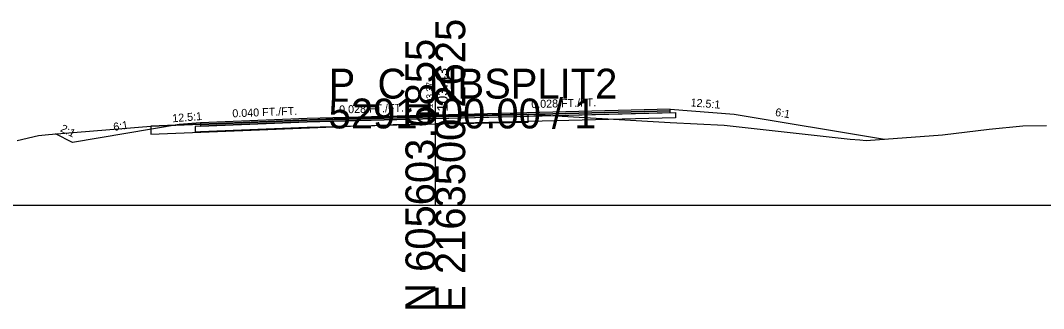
# Model space of a CAD drawing. Extents: x -26 to 1303, y -10 to 12038.
# Drawn here: x 111.1 to 207, y 5990.3 to 6017.3 of the extents above; entities that cross this region are included whole.
import ezdxf

# ---------------------------------------------------------------- set-up
doc = ezdxf.new("R2010")
doc.units = 0
for name, color, linetype in [('RD_GPK_XS_Cell', 7, 'Continuous'), ('RD_XS_Base', 7, 'Continuous'), ('RD_XS_ExGround', 7, 'Continuous'), ('RD_XS_ExPaveRet', 7, 'Continuous'), ('RD_XS_Greenside', 7, 'Continuous'), ('RD_XS_Pave', 7, 'Continuous'), ('RD_XS_PaveOvlay_CP', 7, 'Continuous'), ('RD_XS_TieSlope', 7, 'Continuous'), ('RD_XS_TX_Elev_EX', 7, 'Continuous'), ('RD_XS_TX_Elev_PR', 7, 'Continuous'), ('RD_XS_TX_ShdSlope', 7, 'Continuous'), ('RD_XS_TX_Slope', 7, 'Continuous')]:
    doc.layers.add(name, color=color, linetype=linetype)

msp = doc.modelspace()

# ---------------------------------------------------------------- linework, layer by layer
at = {"layer": 'RD_GPK_XS_Cell'}
for p, q in [((150, 6000), (150, 6010)), ((0, 6000), (150, 6000)), ((150, 6000), (300, 6000))]:
    msp.add_line(p, q, dxfattribs=at)
at = {"layer": 'RD_XS_Base'}
for p, q in [((150, 6008.116), (172.5, 6008.701)), ((150, 6007.616), (150, 6008.275)), ((150, 6008.275), (150, 6008.275)), ((150, 6008.275), (150, 6008.275)), ((150, 6008.275), (150, 6008.116)), ((172.5, 6008.701), (172.5, 6008.201)), ((172.5, 6008.668), (172.5, 6008.668)), ((128, 6007.404), (127.5, 6007.384)), ((127.5, 6007.384), (127.5, 6007.384)), ((127.5, 6007.384), (127.5, 6006.884)), ((138, 6007.804), (128, 6007.404)), ((128, 6007.404), (128, 6007.404)), ((128, 6006.904), (138, 6007.304)), ((150, 6008.116), (138, 6007.804)), ((138, 6007.804), (138, 6007.804)), ((138, 6007.304), (150, 6007.616)), ((138, 6007.304), (138, 6007.304)), ((172.5, 6008.201), (150, 6007.616)), ((150, 6008.116), (150, 6008.116)), ((150, 6007.616), (150, 6008.116)), ((150, 6008.116), (150, 6008.116)), ((150, 6008.116), (150, 6008.116)), ((150, 6007.616), (150, 6007.616)), ((127.5, 6006.884), (128, 6006.904)), ((128, 6006.904), (128, 6006.904))]:
    msp.add_line(p, q, dxfattribs=at)
at = {"layer": 'RD_XS_ExGround'}
msp.add_lwpolyline([(110.806, 6006.081), (112.833, 6006.551), (113.74, 6006.633), (123.35, 6007.417), (139.004, 6008.034), (142.785, 6008.182), (143.202, 6008.196), (144.342, 6008.238), (146.057, 6008.303), (148.56, 6008.342), (158.682, 6008.536), (172.001, 6007.762), (177.051, 6007.512), (188.856, 6006.207), (189.771, 6006.119), (190.368, 6006.053), (197.524, 6006.59), (201.892, 6007.129), (205.042, 6007.446), (207.267, 6007.473)], dxfattribs=at)
at = {"layer": 'RD_XS_ExPaveRet'}
for points in [[(148.56, 6008.342), (146.057, 6008.303), (146.057, 6008.303), (144.342, 6008.238), (144.342, 6008.238), (143.202, 6008.196), (143.202, 6008.196), (142.785, 6008.182), (139.004, 6008.034), (139.004, 6008.034), (123.35, 6007.417), (123.35, 6007.417), (123.35, 6007.417), (123.35, 6006.667), (123.35, 6006.667), (139.004, 6007.284), (139.004, 6007.284), (142.785, 6007.432), (143.202, 6007.446), (143.202, 6007.446), (144.342, 6007.488), (144.342, 6007.488), (146.057, 6007.553), (146.057, 6007.553), (148.56, 6007.592), (148.56, 6007.592), (158.682, 6007.786), (158.682, 6008.536), (158.682, 6008.536), (148.56, 6008.342), (148.56, 6008.342)], [(148.56, 6008.342), (146.057, 6008.303), (144.342, 6008.238), (143.202, 6008.196), (142.785, 6008.182), (139.004, 6008.034), (123.35, 6007.417), (123.35, 6006.667), (139.004, 6007.284), (142.785, 6007.432), (143.202, 6007.446), (144.342, 6007.488), (146.057, 6007.553), (148.56, 6007.592), (158.682, 6007.786), (158.682, 6008.536), (148.56, 6008.342)]]:
    msp.add_lwpolyline(points, dxfattribs=at)
at = {"layer": 'RD_XS_Greenside'}
for p, q in [((178, 6008.526), (192.071, 6006.181)), ((126, 6007.562), (116, 6005.895)), ((116, 6005.895), (114.413, 6006.688))]:
    msp.add_line(p, q, dxfattribs=at)
at = {"layer": 'RD_XS_Pave'}
for p, q in [((150, 6008.434), (138, 6008.122)), ((138, 6007.963), (150, 6008.275)), ((150, 6008.275), (138, 6007.963)), ((172, 6009.006), (150, 6008.434)), ((172, 6008.847), (150, 6008.275)), ((150, 6008.275), (172, 6008.847)), ((150, 6008.116), (172, 6008.688)), ((150, 6008.434), (150, 6008.434)), ((150, 6008.275), (150, 6008.275)), ((150, 6008.275), (150, 6008.275)), ((150, 6008.275), (150, 6008.116)), ((150, 6008.275), (150, 6008.275)), ((150, 6008.116), (150, 6008.275)), ((150, 6008.275), (150, 6008.275)), ((150, 6008.275), (150, 6008.275)), ((172, 6008.847), (172, 6009.006)), ((172, 6009.006), (172, 6009.006)), ((172, 6009.006), (172, 6009.006)), ((172, 6009.006), (172, 6009.006)), ((172, 6008.688), (172, 6008.847)), ((172, 6008.847), (172, 6008.847)), ((172, 6008.847), (172, 6008.847)), ((172, 6008.847), (172, 6008.847)), ((172, 6008.847), (172, 6008.847)), ((172, 6008.847), (172, 6008.847)), ((138, 6008.122), (128, 6007.722)), ((128, 6007.563), (138, 6007.963)), ((138, 6007.963), (128, 6007.563)), ((128, 6007.404), (138, 6007.804)), ((128, 6007.722), (128, 6007.722)), ((128, 6007.722), (128, 6007.563)), ((128, 6007.563), (128, 6007.563)), ((128, 6007.563), (128, 6007.404)), ((138, 6008.122), (138, 6008.122)), ((138, 6007.804), (150, 6008.116)), ((138, 6007.963), (138, 6007.963)), ((138, 6007.963), (138, 6007.963)), ((138, 6007.804), (138, 6007.804)), ((150, 6008.116), (150, 6008.116)), ((150, 6008.116), (150, 6008.116))]:
    msp.add_line(p, q, dxfattribs=at)
at = {"layer": 'RD_XS_PaveOvlay_CP'}
for p, q in [((150, 6008.434), (138, 6008.122)), ((172, 6009.006), (150, 6008.434)), ((150, 6008.434), (150, 6008.434)), ((172, 6009.006), (172, 6009.006)), ((172, 6009.006), (172, 6009.006)), ((138, 6008.122), (128, 6007.722)), ((138, 6008.122), (138, 6008.122))]:
    msp.add_line(p, q, dxfattribs=at)
at = {"layer": 'RD_XS_TieSlope'}
for p, q in [((172, 6009.006), (178, 6008.526)), ((128, 6007.722), (126, 6007.562))]:
    msp.add_line(p, q, dxfattribs=at)

# ---------------------------------------------------------------- texts
at = {"layer": 'RD_GPK_XS_Cell'}
for s, p in [('E 2163500.2625', (152.8, 5990)), ('N 605603.6855', (150, 5990))]:
    msp.add_text(s, height=2.8, rotation=90, dxfattribs=at).set_placement(p)
for s, p in [('P_C_NBSPLIT2', (140, 6010)), ('5291+00.00 / 1', (140, 6007.2))]:
    msp.add_text(s, height=2.8, dxfattribs=at).set_placement(p)
at = {"layer": 'RD_XS_TX_Elev_EX'}
msp.add_text('103.37', height=0.6, rotation=90, dxfattribs=at).set_placement((149.757, 6009.09))
at = {"layer": 'RD_XS_TX_Elev_PR'}
msp.add_text('103.43', height=1, rotation=90, dxfattribs=at).set_placement((151.161, 6008.776))
at = {"layer": 'RD_XS_TX_ShdSlope'}
for rotation, p in [(355.42608, (173.893, 6009.274)), (4.57392, (125.384, 6007.773))]:
    msp.add_text('12.5:1', height=0.75, rotation=rotation, dxfattribs=at).set_placement(p)
at = {"layer": 'RD_XS_TX_Slope'}
for s, rotation, p in [('0.040 FT./FT.', 2.29061, (130.995, 6008.237)), ('0.028 FT./FT.', 1.60386, (140.999, 6008.601)), ('0.028 FT./FT.', 1.60386, (158.999, 6009.105)), ('6:1', 350.53768, (181.8, 6008.379)), ('2:1', 333.43495, (114.793, 6006.957)), ('6:1', 9.46418, (119.893, 6006.958))]:
    msp.add_text(s, height=0.75, rotation=rotation, dxfattribs=at).set_placement(p)

doc.saveas('drawing.dxf')
